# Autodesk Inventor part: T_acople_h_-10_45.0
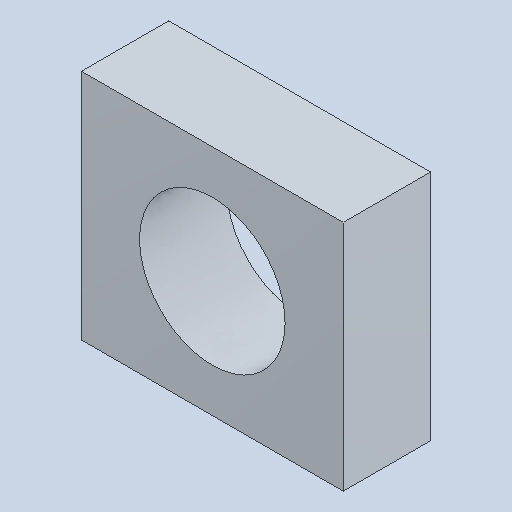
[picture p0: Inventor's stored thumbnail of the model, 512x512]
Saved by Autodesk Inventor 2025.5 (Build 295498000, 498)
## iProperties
Created: 2026-10
Part Number: T_acople_h_-10_45.0
Material: Genérico
Document SubType Name: Modeling
Designer: Luis M
Density: 1 g/cm^3
Appearance: Valor por defecto
Author: Luis M
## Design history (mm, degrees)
feature "Base1"
node "Sólido1"
